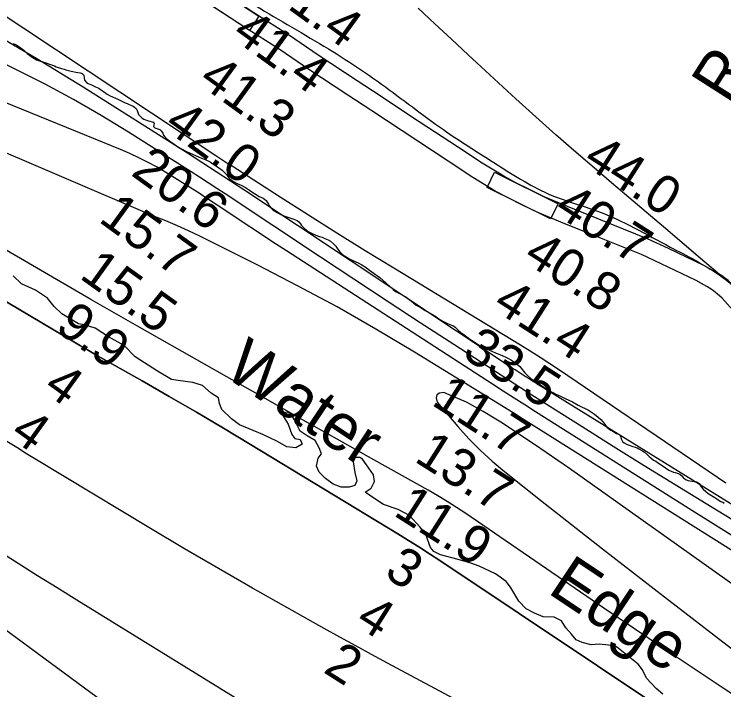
# Model space of a CAD drawing. Extents: x 3187622 to 3225504, y 800805 to 826213.
# Drawn here: x 3202773 to 3204024, y 815461 to 816652 of the extents above; entities that cross this region are included whole.
import ezdxf

# ---------------------------------------------------------------- set-up
doc = ezdxf.new("R2010")
doc.units = 0
for name, color, linetype in [('V-RIVR-EDGE', 7, 'Continuous'), ('V-RIVR-IDEN', 7, 'Continuous'), ('V-RIVR-RANG', 7, 'Continuous'), ('V-RIVR-RANG-IDEN', 7, 'Continuous'), ('V-ROAD-CNTR', 7, 'Continuous'), ('V-SITE-VEGE', 7, 'Continuous'), ('V-TOPO-DPTH', 7, 'Continuous'), ('V-TOPO-MAJR', 7, 'Continuous'), ('V-TOPO-MINR', 7, 'Continuous'), ('V-TOPO-WATR', 7, 'Continuous')]:
    doc.layers.add(name, color=color, linetype=linetype)

msp = doc.modelspace()

# ---------------------------------------------------------------- linework, layer by layer
at = {"layer": 'V-RIVR-EDGE'}
for points in [[(3203662.3, 815616.9), (3203647.2, 815641.3), (3203639.8, 815651.3), (3203621.1, 815664.8), (3203592, 815678.8), (3203577.3, 815683.6), (3203555.1, 815690.2), (3203523.8, 815698.5), (3203512.6, 815704.2), (3203506.5, 815711.2), (3203498.3, 815734.2), (3203487.5, 815747.7), (3203469.7, 815768.2), (3203449.7, 815778.7), (3203423.7, 815787.4), (3203406.3, 815798.4), (3203391.5, 815808.8), (3203401.6, 815816.2), (3203407.7, 815827.9), (3203406, 815839.7), (3203393.4, 815857.5), (3203386.5, 815867.5), (3203381.7, 815870.1), (3203373.9, 815870.2), (3203370.4, 815862.3), (3203372.9, 815843.6), (3203376.4, 815829.3), (3203373.3, 815821), (3203362.9, 815817.6), (3203349, 815818.1), (3203335.1, 815822.9), (3203321.6, 815832.9), (3203309.9, 815844.2), (3203305.6, 815854.7), (3203308.2, 815869), (3203314.3, 815876.8), (3203310, 815887.3), (3203303.1, 815900.3), (3203288.8, 815908.2), (3203276.6, 815916.9), (3203266.7, 815936.9), (3203261.5, 815945.2), (3203255, 815950.4), (3203247.1, 815949.2), (3203246.7, 815943.1), (3203255.4, 815928.7), (3203261.8, 815910.9), (3203267, 815903.9), (3203276.6, 815901.7), (3203280.5, 815893.9), (3203269.2, 815887.4), (3203253.1, 815889.2), (3203235.3, 815898.8), (3203211, 815910.6), (3203194, 815918), (3203169.7, 815928), (3203155.4, 815938.5), (3203138.5, 815955.1), (3203134.6, 815965.5), (3203132.5, 815975.5), (3203119.9, 815983.8), (3203104.3, 815997.3), (3203087.7, 816002.6), (3203061.7, 816005.7), (3203049.9, 816007.5), (3203025.2, 816022.7), (3202985.7, 816048), (3202966.6, 816067.6), (3202938.9, 816082.9), (3202915.4, 816098.2), (3202896.3, 816103.9), (3202885.9, 816106.1), (3202856.4, 816123.6), (3202842.9, 816136.6), (3202831.2, 816151), (3202810, 816165), (3202785.2, 816176.3), (3202770.9, 816190.7)], [(3203916.2, 815452.8), (3203904, 815462.9), (3203887.1, 815481.2), (3203880.2, 815496), (3203872.4, 815506), (3203837.3, 815533.9), (3203831.6, 815538.2), (3203803.8, 815540.9), (3203789.9, 815539.6), (3203773.8, 815544), (3203763.4, 815548.4), (3203754.8, 815558.4), (3203745.2, 815569.7), (3203737.4, 815581.9), (3203724.4, 815588.9), (3203705.3, 815589.4), (3203689.6, 815595.5), (3203674.9, 815603.4), (3203662.3, 815616.9)]]:
    msp.add_lwpolyline(points, dxfattribs=at)
at = {"layer": 'V-ROAD-CNTR'}
for points in [[(3204039.3, 816174.8), (3204031.1, 816182.1), (3204019.9, 816190.7), (3204008.5, 816197.7), (3203988.4, 816209), (3203926, 816239), (3203890.2, 816255.5), (3203824.8, 816281.9), (3203747.7, 816312.8), (3203706.8, 816330.1), (3203681.9, 816342.3), (3203656.9, 816354.7), (3203635.6, 816366.2), (3203597.3, 816389.3), (3203554.2, 816418), (3203473, 816471), (3203417.6, 816507.8), (3203377.3, 816534.5), (3203308.4, 816579.5), (3203258, 816614.1), (3203194.9, 816654.3), (3203109.9, 816710.5), (3203087.1, 816726.5)], [(3204063.3, 816103.1), (3204020.7, 816151.1), (3204011.9, 816159), (3204002.8, 816166), (3203993.4, 816171.8), (3203974.5, 816182.4), (3203913.3, 816211.9), (3203878.3, 816228), (3203813.6, 816254.1), (3203736.3, 816285.1), (3203694.3, 816302.8), (3203668.7, 816315.4), (3203643.1, 816328), (3203620.7, 816340.1), (3203581.2, 816364), (3203537.7, 816392.9), (3203456.5, 816446), (3203401.1, 816482.8), (3203360.8, 816509.4), (3203291.7, 816554.5), (3203241.4, 816589.1), (3203178.6, 816629.1), (3203092.9, 816685.7)]]:
    msp.add_lwpolyline(points, dxfattribs=at)
for points in [[(3203187.4, 816623.3), (3203083.1, 816692.2), (3203099.6, 816717.3), (3203203.9, 816648.3)], [(3203718.1, 816290.9), (3203606.1, 816346.4), (3203619.4, 816373.2), (3203731.4, 816317.8)]]:
    msp.add_lwpolyline(points, close=True, dxfattribs=at)
msp.add_spline([(3201024.1, 823274.7), (3201018, 823194.2), (3201004.7, 822963.7), (3200987.4, 822858.7), (3200966.9, 822788.4), (3200937.8, 822670.8), (3200879.4, 822446.8), (3200861.2, 822331.3), (3200852.3, 822205.9), (3200846, 822103), (3200850.5, 822002.7), (3200859.8, 821900.4), (3200873.1, 821709.1), (3200906.2, 821470.9), (3200956.6, 821171.3), (3200981.8, 821020.5), (3201004.4, 820882.9), (3201024.9, 820767.6), (3201030.7, 820687.4), (3201025.1, 820574.8), (3201019.7, 820485.6), (3201009.9, 820413.7), (3200981.8, 820299.2), (3200938.6, 820153.1), (3200919.7, 820054.1), (3200905.9, 819899.8), (3200911.1, 819808), (3200923.6, 819715), (3200943.7, 819632.5), (3200990, 819544.5), (3201077.6, 819388.7), (3201164.6, 819241.3), (3201215.4, 819169.2), (3201320.5, 819031.2), (3201438.3, 818874.6), (3201472.9, 818830.2), (3201517.8, 818788.5), (3201613.7, 818704.1), (3201703.7, 818596), (3201763.8, 818510.5), (3201836.1, 818397.9), (3201893.8, 818288.1), (3201910, 818246.3), (3201920.9, 818198.1), (3201929.8, 818155.8), (3201937.9, 818094.1), (3201957.7, 817998.6), (3201977.9, 817926.4), (3202055.4, 817776.5), (3202147, 817624), (3202184.4, 817575.3), (3202228.3, 817509.6), (3202265.9, 817465), (3202335.4, 817389.3), (3202595.4, 817156.1), (3202698.6, 817066.2), (3202845.2, 816933.8), (3202967.2, 816832.3), (3203084.1, 816744.2), (3203205.8, 816662.3), (3203334.5, 816585.9), (3203420.1, 816528.7), (3203529.1, 816448.4), (3203624.3, 816386.4), (3203720.3, 816332.5), (3203800.7, 816304.6), (3203929.1, 816241.3), (3204015.1, 816192.4), (3204112.5, 816105.4), (3204200.5, 816023.3)], degree=3, dxfattribs=at)
at = {"layer": 'V-SITE-VEGE'}
for points in [[(3202770.7, 816600.4), (3202773.5, 816599.1), (3202777, 816597.1), (3202783.1, 816593.4), (3202786.6, 816590.7), (3202789.5, 816588.4), (3202795.3, 816582.9), (3202799.6, 816579.6), (3202804.4, 816575.9), (3202811.9, 816571.2), (3202815.3, 816570.2), (3202824.7, 816567.5), (3202839.9, 816561.9), (3202843.4, 816560.7), (3202846.5, 816559.3), (3202856, 816556.1), (3202860.4, 816554.8), (3202863.6, 816554.1), (3202868, 816552.9), (3202873.1, 816551.7), (3202876.2, 816551), (3202881.4, 816550), (3202884.6, 816549.3), (3202888.8, 816548.3), (3202892.6, 816547.1), (3202895.3, 816544.4), (3202895.7, 816539.8), (3202896.4, 816535.8), (3202900.2, 816531.6), (3202903, 816529.8), (3202905.7, 816528.4), (3202908.9, 816527.1), (3202915.7, 816523.9)], [(3202915.7, 816523.9), (3202921.6, 816521.3), (3202924.4, 816519.3), (3202929.8, 816515.8), (3202936.2, 816511), (3202942, 816507.8), (3202955.2, 816502.1), (3202962.2, 816498.4), (3202968.3, 816495.5), (3202971.8, 816494.3), (3202975.5, 816492.6), (3202978.4, 816491.4), (3202982.1, 816489.6), (3202984.9, 816487.9), (3202987.3, 816485.6), (3202989.1, 816482.1), (3202990.4, 816478.4), (3202991.9, 816475.1), (3202994.2, 816472.5), (3202998, 816468.8), (3203001, 816466.8), (3203004.1, 816465.4), (3203009.3, 816463.7), (3203018, 816461.6), (3203019.2, 816458.5), (3203018.2, 816454.1), (3203020.6, 816451.6), (3203023.8, 816450.3), (3203029, 816448.4), (3203031.5, 816446.5), (3203034.5, 816442.1), (3203035.9, 816438.8), (3203038.3, 816435.8), (3203042.3, 816431.7), (3203048.7, 816427), (3203052.1, 816424.4), (3203062.5, 816417), (3203066.2, 816415.3), (3203076.3, 816409.9), (3203098.4, 816399.6), (3203113.4, 816393.9), (3203118.2, 816391.4), (3203122.5, 816388.2), (3203127.5, 816385), (3203133.5, 816381), (3203136.7, 816378.7), (3203139.2, 816377), (3203144.3, 816371.9), (3203146.7, 816369.2), (3203149.3, 816365.6), (3203151.6, 816362.6), (3203155.8, 816359), (3203159.2, 816356.8), (3203165.9, 816353.3), (3203169.5, 816351.6), (3203172.7, 816350.4), (3203180.4, 816346.3), (3203187.6, 816341.8), (3203191.6, 816338.6), (3203196, 816335.8), (3203204.5, 816330.4), (3203211.4, 816327.5), (3203213.8, 816325.7), (3203216.7, 816323.2), (3203218.7, 816320.4), (3203220.8, 816317.1), (3203222.4, 816313.7), (3203224.7, 816310.4), (3203228.4, 816306.9), (3203236.1, 816302.3), (3203241.6, 816299.3), (3203246.6, 816296.9), (3203249.6, 816295.7), (3203260.1, 816292), (3203265.3, 816290.2), (3203268.4, 816289.4), (3203271.3, 816288.2), (3203274.5, 816285.8), (3203277.5, 816282.2), (3203279.2, 816279.6), (3203281.8, 816276.1), (3203289.9, 816269.4), (3203298.9, 816264.9), (3203307.5, 816261), (3203310.5, 816260.1), (3203315.2, 816258.6), (3203320.4, 816256.5), (3203326, 816254), (3203330, 816251.6), (3203335.5, 816246.9), (3203339.5, 816242.8), (3203341.5, 816240.2), (3203345.8, 816233.7), (3203351.5, 816228.1), (3203354.6, 816225.6), (3203364.5, 816219.9), (3203378.7, 816213.4), (3203385.6, 816209.9), (3203393, 816205), (3203396.5, 816202.4), (3203398.9, 816200.4)], [(3203398.9, 816200.4), (3203407, 816194.7), (3203409.7, 816193.2), (3203413.2, 816190.8), (3203417.2, 816187.5), (3203428.2, 816177.9), (3203434.8, 816171.6), (3203440.7, 816166.3), (3203445, 816162.9), (3203449.5, 816160.4), (3203462.7, 816153.6), (3203466.7, 816150.8), (3203470.6, 816147.8), (3203476.3, 816142.7), (3203481.4, 816138.8), (3203484.8, 816137.1), (3203488, 816135.1), (3203491.3, 816133.3), (3203497.2, 816129.4), (3203501.9, 816127), (3203505.6, 816125), (3203510.2, 816122.2), (3203513.8, 816120.2), (3203521.1, 816115), (3203527.1, 816111.3), (3203535, 816107.2), (3203540.4, 816104.8), (3203543.3, 816103.8), (3203547, 816102.1), (3203550.1, 816100), (3203555, 816095), (3203560.1, 816090.7), (3203563.7, 816088.1), (3203570.4, 816082.8), (3203575.5, 816079.1), (3203579.7, 816076.3), (3203582.4, 816074.6), (3203585, 816072.8), (3203596.1, 816065.4), (3203599.1, 816063.9), (3203614.6, 816057.6), (3203622, 816054.2), (3203628.5, 816051.6), (3203639.1, 816047.2), (3203643.8, 816044.5), (3203648.3, 816042.3), (3203652.9, 816039.6), (3203657.1, 816036.8), (3203664.1, 816030.5), (3203666.5, 816027.7), (3203672.9, 816019.4), (3203676.7, 816015.3), (3203683.6, 816009.4), (3203693, 816003.1), (3203697, 816000.6), (3203706.2, 815994.4), (3203713.2, 815989.4), (3203724.2, 815983.6), (3203727.2, 815982.1), (3203731.6, 815980.2), (3203735.6, 815978.1), (3203743.7, 815974), (3203750.3, 815971.1), (3203756.5, 815968.1), (3203767, 815962.5), (3203784.9, 815953.7), (3203788.7, 815951.3), (3203795.6, 815946.7), (3203802.3, 815941.5), (3203806.7, 815937.5), (3203810.8, 815932.7), (3203817.9, 815923.3), (3203821.1, 815920.7), (3203824.5, 815918.6), (3203827.7, 815916.5), (3203834.6, 815912.8), (3203838.2, 815911.1), (3203840.7, 815908.9), (3203842, 815906), (3203842.7, 815903), (3203845.2, 815898.6), (3203848.1, 815896.1), (3203851.8, 815893.6), (3203856.5, 815891.9), (3203863.3, 815889.6), (3203867.5, 815888.6), (3203870.9, 815887.2), (3203873.8, 815885.7), (3203880.2, 815882), (3203883.9, 815879.5), (3203889, 815875.1), (3203891.9, 815872.2), (3203894.7, 815869.5), (3203899.7, 815865.7), (3203903.4, 815863.5), (3203908.4, 815860.1), (3203914.6, 815856.1), (3203926.5, 815847.9), (3203934.6, 815844.5), (3203937.5, 815843.5), (3203943.1, 815842.2)], [(3203943.1, 815842.2), (3203945.9, 815840.9), (3203949.5, 815837.6), (3203951.9, 815835.1), (3203956.2, 815831.6), (3203960.4, 815829.9), (3203963.8, 815829), (3203971, 815828.1), (3203975.5, 815827.2), (3203979.8, 815824.1), (3203981.7, 815821.2), (3203983.8, 815818.2), (3203987.3, 815814.4), (3203996.2, 815806.9), (3204007.6, 815799.7), (3204011.2, 815797.4), (3204015.2, 815794.5), (3204018.5, 815792.7), (3204021.8, 815791.3), (3204024.2, 815789.5)]]:
    msp.add_lwpolyline(points, dxfattribs=at)
at = {"layer": 'V-TOPO-DPTH'}
for points in [[(3204217.8, 815592.6), (3203668.9, 815938.5), (3203655.2, 815947.1), (3203641.4, 815955.7), (3203627.7, 815964.2), (3203613.9, 815972.7), (3203478, 816056), (3203410.2, 816096.5), (3203341.7, 816135.7), (3203272.2, 816173.1), (3203202, 816209.3), (3203099.7, 816260.5), (3203080, 816269.9), (3203060.2, 816279), (3203040.1, 816287.4), (3203019.7, 816295.4), (3202210.8, 816641.7), (3202179.6, 816657.9), (3202148.3, 816673.9), (3202116.9, 816689.7), (3202024, 816735.9), (3201946.1, 816774.7), (3201868.2, 816813.6)], [(3202704.9, 816176.4), (3202877.5, 816074.1), (3202889.5, 816067.1), (3202901.6, 816060.1), (3202913.7, 816053.1), (3202925.8, 816046.2), (3202997.9, 816005.3), (3203046, 815977.8), (3203094, 815950), (3203141.6, 815921.7), (3203189.1, 815893.2), (3203448.6, 815735.7), (3203467.4, 815724.1), (3203486.1, 815712.4), (3203504.6, 815700.5), (3203523, 815688.3), (3203940.8, 815409.2), (3203964, 815393.7), (3203987.1, 815378.1), (3204010.1, 815362.3), (3204033.1, 815346.5)], [(3202704.9, 816176.4), (3202877.5, 816074.1), (3202889.5, 816067.1), (3202901.6, 816060.1), (3202913.7, 816053.1), (3202925.8, 816046.2), (3202997.9, 816005.3), (3203046, 815977.8), (3203094, 815950), (3203141.6, 815921.7), (3203189.1, 815893.2), (3203448.6, 815735.7), (3203467.4, 815724.1), (3203486.1, 815712.4), (3203504.6, 815700.5), (3203523, 815688.3), (3203940.8, 815409.2), (3203964, 815393.7), (3203987.1, 815378.1), (3204010.1, 815362.3), (3204033.1, 815346.5)], [(3204008, 814748.5), (3203837.9, 814833), (3203815.6, 814845.3), (3203794.2, 814858.9), (3203774, 814874.3), (3203754.7, 814891), (3203654.4, 814985.7), (3203310.1, 815350.1), (3203291.1, 815363.8), (3203271.9, 815377.2), (3203252.4, 815390.1), (3203232.6, 815402.7), (3202882.9, 815618.7), (3202848.3, 815640.1), (3202813.8, 815661.6), (3202779.4, 815683.2), (3202745, 815704.9)], [(3204008, 814748.5), (3203837.9, 814833), (3203815.6, 814845.3), (3203794.2, 814858.9), (3203774, 814874.3), (3203754.7, 814891), (3203654.4, 814985.7), (3203310.1, 815350.1), (3203291.1, 815363.8), (3203271.9, 815377.2), (3203252.4, 815390.1), (3203232.6, 815402.7), (3202882.9, 815618.7), (3202848.3, 815640.1), (3202813.8, 815661.6), (3202779.4, 815683.2), (3202745, 815704.9)]]:
    msp.add_lwpolyline(points, dxfattribs=at)
at = {"layer": 'V-TOPO-MAJR'}
msp.add_lwpolyline([(3204255.2, 815652.9), (3203706.2, 815992.5), (3203701.3, 815995.5), (3203696.3, 815998.6), (3203691.4, 816001.7), (3203686.5, 816004.8), (3203678.5, 816009.9), (3203677.7, 816010.4), (3203675.9, 816011.6), (3203675, 816012.1), (3203666.3, 816017.8), (3203661.1, 816021.2), (3203655.8, 816024.6), (3203650.6, 816028), (3203645.4, 816031.5), (3203179.2, 816341.1), (3203154, 816357.7), (3203128.8, 816374.2), (3203103.5, 816390.5), (3203078, 816406.8), (3202894.2, 816523.3), (3202812.3, 816573.3), (3202729.4, 816621.4), (3202645, 816666.8)], dxfattribs=at)
at = {"layer": 'V-TOPO-MINR'}
for points in [[(3204027.1, 815824.8), (3203733.7, 816024.2), (3203716.7, 816035.6), (3203699.6, 816046.7), (3203682.3, 816057.6), (3203665, 816068.4), (3203441.7, 816204), (3203391.4, 816234.9), (3203341.2, 816266), (3203291.3, 816297.4), (3203241.6, 816329.1), (3203156.6, 816383.7), (3203149.4, 816388.3), (3203142.3, 816393), (3203135.2, 816397.6), (3203128.1, 816402.3), (3202564.1, 816776.6), (3202531, 816798.2), (3202497.7, 816819.6), (3202464.1, 816840.5), (3202430.4, 816861.1), (3202427.8, 816862.7), (3201556.2, 817191.3)], [(3204217.8, 815592.6), (3203668.9, 815938.5), (3203655.2, 815947.1), (3203641.4, 815955.7), (3203627.7, 815964.2), (3203613.9, 815972.7), (3203478, 816056), (3203410.2, 816096.5), (3203341.7, 816135.7), (3203272.2, 816173.1), (3203202, 816209.3), (3203099.7, 816260.5), (3203080, 816269.9), (3203060.2, 816279), (3203040.1, 816287.4), (3203019.7, 816295.4), (3202210.8, 816641.7), (3202179.6, 816657.9), (3202148.3, 816673.9), (3202116.9, 816689.7), (3202024, 816735.9), (3201946.1, 816774.7), (3201868.2, 816813.6)], [(3204066.1, 815714.9), (3204018.8, 815744.2), (3203971.6, 815773.8), (3203691.7, 815950.8), (3203672.7, 815962.8), (3203653.7, 815974.9), (3203634.8, 815987.1), (3203615.9, 815999.3), (3203252.4, 816234.9), (3203226.9, 816251.4), (3203201.6, 816268), (3203176.2, 816284.7), (3203150.9, 816301.4), (3203109.9, 816328.6), (3203105.1, 816331.8), (3203100.3, 816334.9), (3203095.5, 816338), (3203090.7, 816341.1), (3203055.2, 816363.5), (3203039.9, 816372.9), (3203024.3, 816381.9), (3203008.5, 816390.4), (3202992.5, 816398.5), (3202976.2, 816406.1), (3202959.8, 816413.4), (3202273.9, 816692.9)], [(3204049.4, 816164.5), (3203989.9, 816214.7), (3203917.1, 816277.1), (3203894.3, 816296.5), (3203871.5, 816315.9), (3203848.7, 816335.3), (3203825.8, 816354.6), (3203799.1, 816377.2), (3203763, 816408), (3203727.3, 816439.1), (3203691.9, 816470.8), (3203656.9, 816502.8), (3203573, 816580.4), (3203543.6, 816607.7), (3203514.2, 816635.2), (3203484.9, 816662.7)], [(3204226.4, 815645.9), (3203992.5, 815788.3), (3203937.6, 815821.9), (3203882.9, 815855.7), (3203828.3, 815889.8), (3203773.9, 815924.1), (3203685.1, 815980.3), (3203675.2, 815986.6), (3203665.3, 815993), (3203655.3, 815999.3), (3203645.4, 816005.7), (3203547.4, 816069.3), (3203488.5, 816107.6), (3203429.8, 816146.1), (3203371.1, 816184.7), (3203312.5, 816223.4), (3203144.6, 816334.9), (3203129.6, 816344.7), (3203114.6, 816354.6), (3203099.5, 816364.3), (3203084.4, 816373.9), (3202974.2, 816443.7), (3202925.8, 816473.3), (3202876.9, 816501.7), (3202827, 816528.4), (3202776.5, 816554.1), (3202739.6, 816572.1)], [(3204114.4, 815403.1), (3204022.4, 815463.5), (3203969.6, 815498.5), (3203916.8, 815533.7), (3203864.3, 815569.1), (3203811.9, 815604.8), (3203568.8, 815771.3), (3203552.5, 815782.1), (3203536.1, 815792.6), (3203519.4, 815802.7), (3203502.5, 815812.5), (3203406.7, 815866.2), (3203341.8, 815902.7), (3203276.9, 815939.2), (3203212.1, 815975.8), (3203147.3, 816012.5), (3202989.9, 816101.6), (3202969.3, 816113.4), (3202948.7, 816125.2), (3202928.1, 816137), (3202907.5, 816148.9), (3202812.1, 816204.4), (3202743.8, 816244)], [(3204159.2, 815560.9), (3203751.2, 815850.7), (3203730.8, 815864.9), (3203710.4, 815879.1), (3203689.9, 815893), (3203669.2, 815906.9), (3203633.5, 815930.5), (3203630.6, 815932.4), (3203627.7, 815934.2), (3203624.8, 815936), (3203621.9, 815937.8), (3203599.1, 815951.5), (3203584.5, 815959.7), (3203569.8, 815967.5), (3203554.6, 815974.5), (3203539.2, 815981), (3203530.2, 815984.6), (3203522.5, 815983.6), (3203517.5, 815980.8), (3203516.4, 815975.2), (3203518.1, 815967.6), (3203554.8, 815924.6), (3203574, 815903.4), (3203593.9, 815883.1), (3203615, 815863.9), (3203636.8, 815845.6), (3203700.6, 815795), (3203755, 815752), (3203809.5, 815709.3), (3203864.2, 815666.7), (3203919, 815624.3), (3204127.2, 815463.8)], [(3204038.9, 815167.8), (3204020.1, 815179.3), (3204001.3, 815190.7), (3203982.4, 815201.8), (3203963.4, 815212.9), (3203859.3, 815272.7), (3203788, 815313.2), (3203716.4, 815353.3), (3203644.5, 815392.8), (3203572.4, 815431.8), (3203430.7, 815507.6), (3203402.6, 815522.7), (3203374.6, 815537.9), (3203346.6, 815553.3), (3203318.8, 815568.8), (3203253.3, 815605.5), (3203192.8, 815639.7), (3203132.6, 815674.2), (3203072.8, 815709.4), (3203013.1, 815744.9), (3202811.7, 815866.2), (3202794.3, 815876.8), (3202776.9, 815887.6), (3202759.6, 815898.5)], [(3204008, 814748.5), (3203837.9, 814833), (3203815.6, 814845.3), (3203794.2, 814858.9), (3203774, 814874.3), (3203754.7, 814891), (3203654.4, 814985.7), (3203310.1, 815350.1), (3203291.1, 815363.8), (3203271.9, 815377.2), (3203252.4, 815390.1), (3203232.6, 815402.7), (3202882.9, 815618.7), (3202848.3, 815640.1), (3202813.8, 815661.6), (3202779.4, 815683.2), (3202745, 815704.9)], [(3203760.4, 814760.1), (3203741, 814774.2), (3203721.8, 814788.5), (3203702.7, 814803), (3203601.1, 814880.6), (3203532.1, 814935), (3203464.3, 814990.8), (3203398.2, 815048.5), (3203333.2, 815107.6), (3203207.1, 815225.8), (3203196.2, 815235.9), (3203185.1, 815245.8), (3203173.9, 815255.4), (3203162.5, 815265), (3203151, 815274.3), (3203139.3, 815283.5), (3203127.5, 815292.6), (3203115.7, 815301.5), (3202627.3, 815661.5)]]:
    msp.add_lwpolyline(points, dxfattribs=at)
at = {"layer": 'V-TOPO-WATR'}
msp.add_lwpolyline([(3204033.1, 815346.5), (3204010.1, 815362.3), (3203987.1, 815378.1), (3203964, 815393.7), (3203940.8, 815409.2), (3203523, 815688.3), (3203504.6, 815700.5), (3203486.1, 815712.4), (3203467.4, 815724.1), (3203448.6, 815735.7), (3203189.1, 815893.2), (3203141.6, 815921.7), (3203094, 815950), (3203046, 815977.8), (3202997.9, 816005.3), (3202925.8, 816046.2), (3202913.7, 816053.1), (3202901.6, 816060.1), (3202889.5, 816067.1), (3202877.5, 816074.1), (3202704.9, 816176.4)], dxfattribs=at)

# ---------------------------------------------------------------- texts
at = {"layer": 'V-RIVR-IDEN'}
for s, p in [('Water', (3203139.2, 816015.7)), ('Edge', (3203710.9, 815632.4))]:
    msp.add_text(s, height=83, rotation=326.3099, dxfattribs=at).set_placement(p)
at = {"layer": 'V-RIVR-RANG'}
for s, rotation, p in [('41.4', 323.9883, (3203212.3, 816692.5)), ('41.4', 323.9883, (3203153.7, 816611.4)), ('41.3', 323.9883, (3203095.1, 816530.4)), ('42.0', 323.9883, (3203034.2, 816451.1)), ('44.0', 327.2883, (3203772.8, 816387.4)), ('20.6', 323.9883, (3202976.4, 816369.4)), ('40.7', 327.2883, (3203721.4, 816301.5)), ('15.7', 323.9883, (3202919.3, 816287.3)), ('40.8', 327.2883, (3203667.6, 816217.3)), ('15.5', 324.2687, (3202885.6, 816187.7)), ('41.4', 327.2883, (3203613.8, 816133)), ('9.9', 324.2687, (3202842.6, 816095.4)), ('33.5', 327.2883, (3203559.9, 816048.7)), ('4', 324.2687, (3202821.3, 815987.6)), ('11.7', 327.2883, (3203506.1, 815964.4)), ('4', 324.2687, (3202762.7, 815906.5)), ('13.7', 327.5701, (3203475.9, 815864.5)), ('11.9', 327.5701, (3203439.2, 815769.3)), ('3', 327.5701, (3203422.6, 815661.4)), ('4', 327.5701, (3203371.6, 815575.3)), ('2', 327.5701, (3203315.4, 815492.6))]:
    msp.add_text(s, height=67, rotation=rotation, dxfattribs=at).set_placement(p)
at = {"layer": 'V-RIVR-RANG-IDEN'}
msp.add_text('R-276.35', height=83, rotation=57.4319, dxfattribs=at).set_placement((3204032.2, 816490.9))

doc.saveas('drawing.dxf')
